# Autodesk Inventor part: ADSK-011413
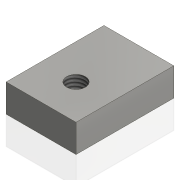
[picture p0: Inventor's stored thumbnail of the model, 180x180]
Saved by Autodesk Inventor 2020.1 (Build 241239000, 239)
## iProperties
Created: 1999-12
Part Number: ADSK-011413
Material: Pearson HRS
Document SubType Name: Modeling
Designer: cmcgourin
Density: 7.83 g/cm^3
Appearance: Steel
Mass: 65.7954 g
Surface Area: 30.8942 cm^2
Volume: 8.40299 cm^3
Control State: 0
Master: False
Checked Out: False
Shininess: 25.0
Length Units: 11269
Angle Units: 11279
Time Units: 11290
Mass Units: 11283
Length Display Precision: 3
Angle Display Precision: 2
Compacted: True
Cutlength: 1.38
Material Desc: FLAT,HRS,0.375X01.000
Material_Number: A084396
Dimensions: 10x35x25 mm
Mass: 0,066 kg
VLT_Material: Pearson HRS
Density: 7.83
Volumn: 7.994697562794077
Area: 30.612066977294575
PropertySet Name: Model Information
Author: cmcgourin
Revision Number: -
Title: ADSK-011413
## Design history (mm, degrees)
node "Solide1"
  node "Extrusion1" dims "d2" = 35, "d3" = 0
  node "Hole1" dims "d5" = 6.647, "d6" = 9.525, "d7" = 6.35, "d8" = 60 deg, "d9" = 19.05, "d10" = 118 deg, "d11" = 16
sketch "Sketch1"
  geometry: L1 (12.5, 5)-(-12.5, 5); L2 (-12.5, 5)-(-12.5, -5); L3 (-12.5, -5)-(12.5, -5); L4 (12.5, -5)-(12.5, 5); 3 further points
  constraints: 8 end point, 2 midpoint, 2 parallel, 1 horizontal, 1 horizontal alignment, 1 perpendicular, 1 vertical alignment
  dimensions: "d0" = 10 distance of L1.end L2.end; "d1" = 25 distance of L1.start L1.end
sketch "Sketch2"
  geometry: L1 (0, -35)-(25, -35) reference; 2 further points
  constraints: 1 midpoint, 1 vertical alignment
  dimensions: "d4" = 12.5 distance from line of L1 point (12.5, -22.5)
node "Corps solides"
node "Corps surfaciques"
